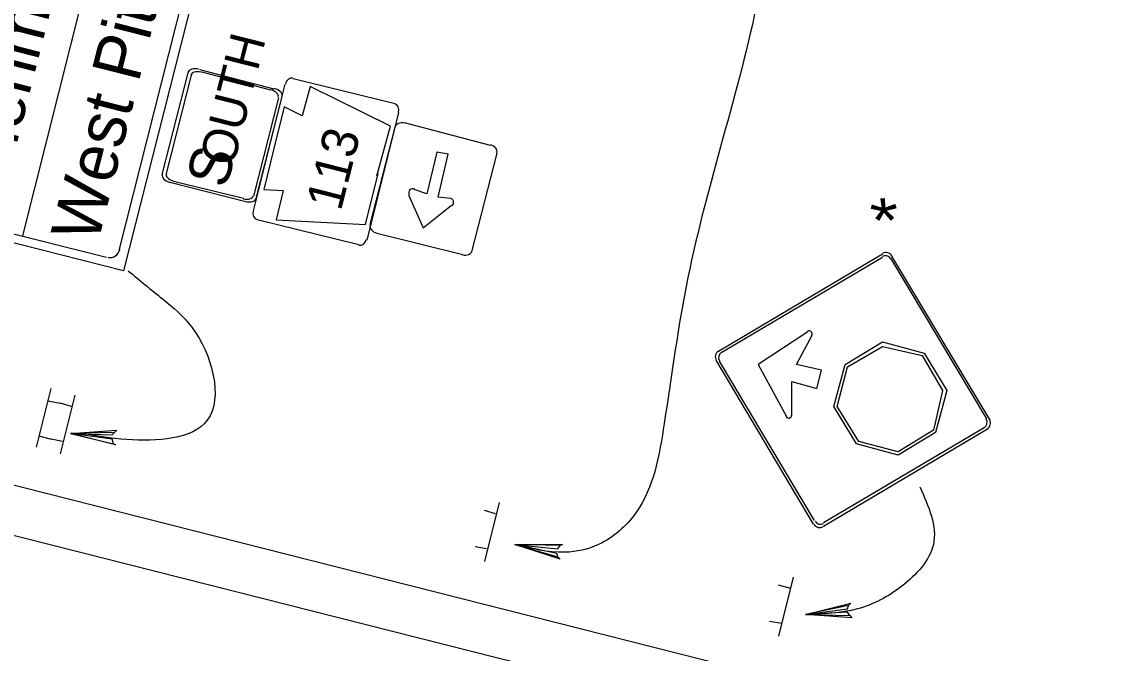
# Model space of a CAD drawing. Extents: x 644898 to 648326, y 298294 to 300670.
# Drawn here: x 647909.2 to 648029.8, y 300456 to 300525.8 of the extents above; entities that cross this region are included whole.
import ezdxf

# ---------------------------------------------------------------- set-up
doc = ezdxf.new("R2010")
doc.units = 0
doc.layers.add('2', color=7, linetype='Continuous')

msp = doc.modelspace()

# ---------------------------------------------------------------- linework, layer by layer
at = {"layer": '2'}
for p, q in [((647909.32, 300502.12), (647927.7, 300575.24)), ((647939.45, 300573.49), (647920.45, 300498.24)), ((647919.95, 300500.49), (647937.95, 300571.49)), ((647924.7, 300508.87), (647927.57, 300520.12)), ((647928.82, 300520.49), (647937.07, 300518.37)), ((647929.07, 300520.24), (647936.7, 300518.24)), ((647925.2, 300508.99), (647927.95, 300519.87)), ((647934.82, 300504.87), (647938.32, 300518.87)), ((647939.2, 300519.49), (647950.45, 300516.74)), ((647941.07, 300518.62), (647940.2, 300515.37)), ((647949.95, 300514.24), (647941.07, 300518.62)), ((647937.57, 300517.37), (647934.82, 300506.49)), ((647937.95, 300517.49), (647935.07, 300506.24)), ((647938.2, 300516.37), (647937.07, 300511.74)), ((647940.2, 300515.37), (647938.2, 300516.37)), ((647950.82, 300515.74), (647947.32, 300501.62)), ((647947.7, 300503.37), (647950.45, 300514.12)), ((647947.7, 300503.37), (647950.45, 300514.12)), ((647947.7, 300503.37), (647950.45, 300514.12)), ((647948.45, 300508.74), (647949.95, 300514.24)), ((647951.45, 300514.62), (647960.95, 300512.12)), ((647951.45, 300514.62), (647960.95, 300512.12)), ((647951.45, 300514.62), (647960.95, 300512.12)), ((647931.32, 300513.24), (647931.32, 300513.24)), ((647937.07, 300511.74), (647935.95, 300507.24)), ((647955.07, 300511.37), (647953.95, 300506.74)), ((647956.32, 300511.12), (647955.07, 300511.37)), ((647955.2, 300506.37), (647956.32, 300511.12)), ((647961.7, 300511.24), (647958.95, 300500.49)), ((647961.7, 300511.24), (647958.95, 300500.49)), ((647961.7, 300511.24), (647958.95, 300500.49)), ((647942.82, 300510.24), (647942.82, 300510.24)), ((647942.82, 300510.24), (647942.82, 300510.24)), ((647933.95, 300505.87), (647925.57, 300507.99)), ((647933.7, 300506.24), (647925.95, 300508.12)), ((647947.2, 300503.37), (647948.57, 300508.99)), ((647920.45, 300498.24), (647886.7, 300506.74)), ((647888.7, 300507.24), (647918.57, 300499.74)), ((647935.95, 300507.24), (647938.07, 300507.12)), ((647938.07, 300507.12), (647937.32, 300503.87)), ((647953.95, 300506.74), (647952.57, 300507.24)), ((647954.7, 300507.24), (647954.7, 300507.24)), ((647954.7, 300507.24), (647954.7, 300507.24)), ((647951.95, 300506.62), (647953.57, 300502.99)), ((647956.57, 300506.24), (647955.2, 300506.37)), ((647953.57, 300502.99), (647956.7, 300505.49)), ((647946.45, 300501.12), (647935.2, 300503.87)), ((647937.32, 300503.87), (647947.2, 300503.37)), ((647957.95, 300499.99), (647948.45, 300502.37)), ((647957.95, 300499.99), (647948.45, 300502.37)), ((647957.95, 300499.99), (647948.45, 300502.37)), ((647946.45, 300501.12), (647946.45, 300501.12)), ((647986.2, 300489.37), (648004.32, 300500.12)), ((647986.57, 300489.24), (648004.32, 300499.74)), ((648005.2, 300499.62), (648015.82, 300481.87)), ((648005.32, 300499.87), (648016.2, 300481.74)), ((647996.07, 300491.49), (647990.57, 300487.87)), ((647996.07, 300491.49), (647990.57, 300487.87)), ((647994.82, 300487.87), (647996.57, 300491.12)), ((647994.82, 300487.87), (647996.57, 300491.12)), ((647989.82, 300453.87), (647844.32, 300490.74)), ((647996.7, 300470.24), (647985.95, 300488.37)), ((647996.82, 300470.62), (647986.32, 300488.24)), ((647990.57, 300487.87), (647993.7, 300482.12)), ((647990.57, 300487.87), (647993.7, 300482.12)), ((647997.57, 300487.24), (647994.82, 300487.87)), ((647997.57, 300487.24), (647994.82, 300487.87)), ((647997.07, 300485.24), (647997.57, 300487.24)), ((647997.07, 300485.24), (647997.57, 300487.24)), ((647910.82, 300478.74), (647912.45, 300485.24)), ((647994.32, 300482.24), (647994.32, 300485.99)), ((647994.32, 300485.99), (647997.07, 300485.24)), ((647994.32, 300482.24), (647994.32, 300485.99)), ((647994.32, 300485.99), (647997.07, 300485.24)), ((647912.07, 300483.87), (647913.45, 300483.62)), ((647915.07, 300484.49), (647913.45, 300477.99)), ((647914.7, 300483.24), (647913.45, 300483.62)), ((648029.82, 300438.24), (647855.82, 300482.24)), ((648015.57, 300480.87), (647997.82, 300470.37)), ((648015.95, 300480.74), (647997.82, 300469.99)), ((647911.07, 300479.99), (647912.45, 300479.62)), ((647913.7, 300479.37), (647912.45, 300479.62)), ((647961.95, 300472.62), (647960.32, 300466.12)), ((647961.57, 300471.37), (647960.32, 300471.74)), ((647960.57, 300467.49), (647959.32, 300467.74)), ((647994.45, 300464.37), (647992.82, 300457.87)), ((647994.2, 300463.12), (647992.82, 300463.49)), ((647993.82, 300463.37), (647993.82, 300463.37)), ((647993.2, 300459.24), (647991.82, 300459.49))]:
    msp.add_line(p, q, dxfattribs=at)
for points in [[(648010.2, 300480.37), (648006.07, 300477.87), (648001.45, 300479.12), (647998.95, 300483.24), (648000.2, 300487.87), (648004.32, 300490.37), (648008.95, 300489.12), (648011.45, 300484.99), (648010.2, 300480.37)], [(648009.95, 300480.62), (648006.07, 300478.24), (648001.7, 300479.37), (647999.32, 300483.24), (648000.45, 300487.62), (648004.32, 300489.87), (648008.7, 300488.87), (648010.95, 300484.99), (648009.95, 300480.62)], [(648009.95, 300480.62), (648006.07, 300478.24), (648001.7, 300479.37), (647999.32, 300483.24), (648000.45, 300487.62), (648004.32, 300489.87), (648008.7, 300488.87), (648010.95, 300484.99), (648009.95, 300480.62)], [(647919.32, 300479.12), (647919.2, 300479.62), (647914.57, 300480.24), (647919.32, 300479.12), (647919.57, 300478.99), (647914.57, 300480.24), (647919.2, 300480.12), (647919.45, 300480.37), (647914.57, 300480.24), (647919.7, 300480.62), (647919.45, 300480.37)], [(647968.45, 300466.62), (647968.32, 300466.99), (647963.7, 300467.99), (647968.45, 300466.62), (647968.7, 300466.37), (647963.7, 300467.99), (647968.45, 300467.49), (647968.7, 300467.87), (647963.7, 300467.99), (647968.95, 300467.99), (647968.7, 300467.87)], [(648000.7, 300460.12), (648000.45, 300460.49), (647995.82, 300460.24), (648000.7, 300460.12), (648000.95, 300459.87), (647995.82, 300460.24), (648000.45, 300460.87), (648000.57, 300461.24), (647995.82, 300460.24), (648000.82, 300461.49), (648000.57, 300461.24)]]:
    msp.add_lwpolyline(points, dxfattribs=at)
for centre, radius, start, end in [((647952.42, 300506.86), 0.46, 64.0256, 207.9322), ((647956.46, 300505.81), 0.46, 305.6371, 86.3026), ((648004.64, 300499.21), 0.69, 30.7754, 120.7754), ((648004.72, 300499.51), 0.753, 30.7754, 120.7754), ((647996.23, 300491.27), 0.326, 331.4732, 123.1918), ((647996.23, 300491.27), 0.326, 331.4732, 123.1918), ((647986.6, 300488.72), 0.753, 120.7754, 210.7754), ((647986.9, 300488.65), 0.69, 120.7754, 210.7754), ((647993.96, 300482.28), 0.326, 208.359, 0.0776), ((647993.96, 300482.28), 0.326, 208.359, 0.0776), ((648015.2, 300481.47), 0.69, 300.7754, 30.7754), ((648015.5, 300481.4), 0.753, 300.7754, 30.7754), ((647997.47, 300470.91), 0.69, 210.7754, 300.7754), ((647997.39, 300470.61), 0.753, 210.7754, 300.7754)]:
    msp.add_arc(centre, radius, start, end, dxfattribs=at)
for centre, major_axis, ratio, start_param, end_param in [((647928.6, 300519.89), (-1.04, 0.26), 0.6, 4.712389, 6.283185), ((647928.86, 300519.62), (-0.964, 0.244), 0.6, 4.712389, 6.283185), ((647938.96, 300518.76), (-0.198, -0.782), 0.8, 3.141593, 4.712389), ((647936.58, 300517.67), (-0.964, 0.244), 0.6, 3.141593, 4.712389), ((647936.94, 300517.77), (-1.04, 0.26), 0.6, 3.141593, 4.712389), ((647950.22, 300515.91), (0.198, 0.782), 0.8, 4.712389, 6.283185), ((647951.33, 300513.87), (-0.903, 0.229), 0.769266, 4.712389, 6.283185), ((647951.33, 300513.87), (-0.903, 0.229), 0.769266, 4.712389, 6.283185), ((647951.33, 300513.87), (-0.903, 0.229), 0.769266, 4.712389, 6.283185), ((647960.81, 300511.47), (-0.903, 0.229), 0.769266, 3.141593, 4.712389), ((647960.81, 300511.47), (-0.903, 0.229), 0.769266, 3.141593, 4.712389), ((647960.81, 300511.47), (-0.903, 0.229), 0.769266, 3.141593, 4.712389), ((647925.75, 300508.63), (1.04, -0.26), 0.6, 3.141593, 4.712389), ((647926.11, 300508.74), (0.964, -0.244), 0.6, 3.141593, 4.712389), ((647933.82, 300506.78), (0.964, -0.244), 0.6, 4.712389, 6.283185), ((647934.09, 300506.52), (1.04, -0.26), 0.6, 4.712389, 6.283185), ((647935.4, 300504.69), (-0.198, -0.782), 0.8, 4.712389, 6.283185), ((647948.6, 300503.1), (0.903, -0.229), 0.769266, 3.141593, 4.712389), ((647948.6, 300503.1), (0.903, -0.229), 0.769266, 3.141593, 4.712389), ((647948.6, 300503.1), (0.903, -0.229), 0.769266, 3.141593, 4.712389), ((647946.65, 300501.84), (0.198, 0.782), 0.8, 3.141593, 4.712389), ((647919.02, 300500.88), (0.29, 1.16), 0.890186, 3.141593, 4.712389), ((647958.08, 300500.7), (0.903, -0.229), 0.769266, 4.712389, 6.283185), ((647958.08, 300500.7), (0.903, -0.229), 0.769266, 4.712389, 6.283185), ((647958.08, 300500.7), (0.903, -0.229), 0.769266, 4.712389, 6.283185)]:
    msp.add_ellipse(centre, major_axis=major_axis, ratio=ratio, start_param=start_param, end_param=end_param, dxfattribs=at)
for points in [[(647994.07, 300562.49), (647990.57, 300528.37), (647982.82, 300497.49), (647980.2, 300481.37), (647977.07, 300471.49), (647972.95, 300467.99), (647969.2, 300467.12), (647963.7, 300467.99)], [(647920.95, 300498.24), (647924.73, 300495.15), (647928, 300492), (647929.69, 300481.71), (647920.79, 300479.59), (647915.95, 300480.24)], [(648008.45, 300474.37), (648009.95, 300467.99), (648006.45, 300463.37), (648001.57, 300460.87), (647995.82, 300460.24)]]:
    msp.add_spline(points, degree=3, dxfattribs=at)

# ---------------------------------------------------------------- texts
for s, height, rotation, p in [('West Pittstown 24', 5.3752, 75.7788, (647917.57, 300501.12)), ('Glenmoore   ', 5.3752, 75.7788, (647907.22, 300506.62)), ('OUTH', 3.875, 75.7783, (647932.57, 300509.62)), ('113', 4, 75.7777, (647944.45, 300504.74)), ('S', 4.63, 75.7284, (647931.82, 300507.24)), ('*', 5.42, 75.7789, (648007.99, 300502.62))]:
    msp.add_text(s, height=height, rotation=rotation, dxfattribs=at).set_placement(p)

doc.saveas('drawing.dxf')
